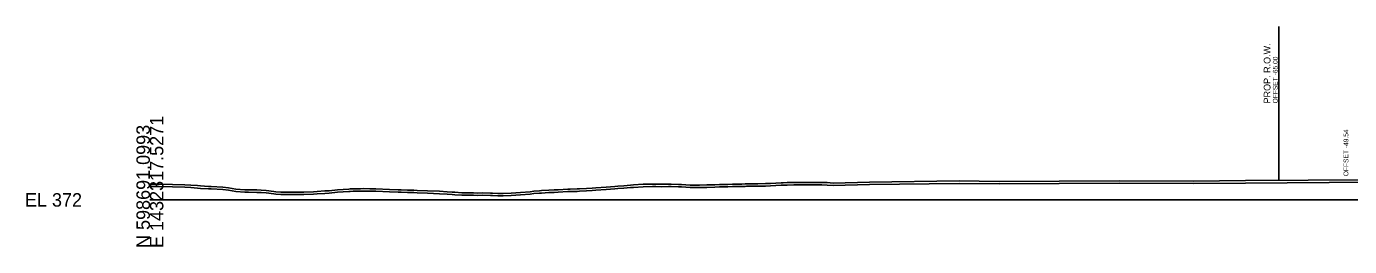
# Model space of a CAD drawing. Extents: x -26 to 2203, y -10 to 12201.
# Drawn here: x -25.7 to 249.7, y 8490.3 to 8536.1 of the extents above; entities that cross this region are included whole.
import ezdxf

# ---------------------------------------------------------------- set-up
doc = ezdxf.new("R2010")
doc.units = 0
for name, color, linetype in [('DESIGN - ROW - Right-of-Way and Easement Labels', 7, 'Continuous'), ('DESIGN - ROW - Right-of-Way Linework', 7, 'Continuous'), ('DESIGN - SHEET - Light Grid', 7, 'Continuous'), ('DESIGN - TYPICAL - Slope Tie Text', 7, 'Continuous'), ('SURVEY - GROUND - Bottom of Topsoil Layer', 7, 'Continuous'), ('SURVEY - GROUND - Top of Ground', 7, 'Continuous')]:
    doc.layers.add(name, color=color, linetype=linetype)

msp = doc.modelspace()

# ---------------------------------------------------------------- linework, layer by layer
at = {"layer": 'DESIGN - ROW - Right-of-Way Linework'}
msp.add_line((235, 8504.06), (235, 8536.06), dxfattribs=at)
at = {"layer": 'DESIGN - SHEET - Light Grid'}
msp.add_line((0, 8500), (300, 8500), dxfattribs=at)
at = {"layer": 'SURVEY - GROUND - Bottom of Topsoil Layer'}
for p, q in [((0, 8502.79), (0.47, 8502.78)), ((0.47, 8502.78), (1.96, 8502.76)), ((1.96, 8502.76), (4.69, 8502.7)), ((4.69, 8502.7), (7.26, 8502.66)), ((7.26, 8502.66), (8.55, 8502.56)), ((8.55, 8502.56), (9.91, 8502.47)), ((9.91, 8502.47), (10.51, 8502.4)), ((10.51, 8502.4), (12.21, 8502.31)), ((12.21, 8502.31), (12.75, 8502.27)), ((12.75, 8502.27), (15.21, 8502.15)), ((15.21, 8502.15), (16.39, 8502.01)), ((16.39, 8502.01), (17.86, 8501.72)), ((17.86, 8501.72), (19.74, 8501.62)), ((19.74, 8501.62), (20.51, 8501.59)), ((20.51, 8501.59), (22.27, 8501.57)), ((22.27, 8501.57), (23.16, 8501.51)), ((37.3, 8501.41), (39.07, 8501.58)), ((39.07, 8501.58), (41.39, 8501.75)), ((41.39, 8501.75), (41.72, 8501.78)), ((41.72, 8501.78), (42.32, 8501.79)), ((42.32, 8501.79), (43.83, 8501.83)), ((43.83, 8501.83), (44.37, 8501.84)), ((44.37, 8501.84), (45.79, 8501.83)), ((45.79, 8501.83), (47.02, 8501.79)), ((47.02, 8501.79), (49.84, 8501.67)), ((49.84, 8501.67), (51.68, 8501.6)), ((51.68, 8501.6), (52.32, 8501.6)), ((52.32, 8501.6), (53.64, 8501.54)), ((83.04, 8501.51), (84.13, 8501.56)), ((84.13, 8501.56), (85, 8501.61)), ((85, 8501.61), (86.96, 8501.72)), ((86.96, 8501.72), (87.48, 8501.73)), ((87.48, 8501.73), (88.92, 8501.78)), ((88.92, 8501.78), (89.43, 8501.81)), ((89.43, 8501.81), (90.88, 8501.9)), ((90.88, 8501.9), (92.08, 8501.96)), ((92.08, 8501.96), (92.84, 8502.04)), ((92.84, 8502.04), (95, 8502.17)), ((95, 8502.17), (96.76, 8502.31)), ((96.76, 8502.31), (97.38, 8502.34)), ((97.38, 8502.34), (98.67, 8502.44)), ((98.67, 8502.44), (100.03, 8502.55)), ((100.03, 8502.55), (100.68, 8502.61)), ((100.68, 8502.61), (102.68, 8502.75)), ((102.68, 8502.75), (104.6, 8502.76)), ((104.6, 8502.76), (105.33, 8502.78)), ((105.33, 8502.78), (106.56, 8502.75)), ((106.56, 8502.75), (107.98, 8502.78)), ((107.98, 8502.78), (108.52, 8502.77)), ((108.52, 8502.77), (110.06, 8502.72)), ((110.06, 8502.72), (110.63, 8502.7)), ((110.63, 8502.7), (112.44, 8502.59)), ((112.44, 8502.59), (113.28, 8502.56)), ((113.28, 8502.56), (114.4, 8502.55)), ((114.4, 8502.55), (115.94, 8502.6)), ((115.94, 8502.6), (117.58, 8502.66)), ((117.58, 8502.66), (118.59, 8502.69)), ((118.59, 8502.69), (120.29, 8502.73)), ((120.29, 8502.73), (121.24, 8502.76)), ((121.24, 8502.76), (123.22, 8502.8)), ((123.22, 8502.8), (123.89, 8502.82)), ((123.89, 8502.82), (124.21, 8502.83)), ((124.21, 8502.83), (125.11, 8502.84)), ((125.11, 8502.84), (126.17, 8502.85)), ((126.17, 8502.85), (126.54, 8502.87)), ((126.54, 8502.87), (128.13, 8502.88)), ((128.13, 8502.88), (129.19, 8502.94)), ((129.19, 8502.94), (131.41, 8503.04)), ((131.41, 8503.04), (131.84, 8503.05)), ((131.84, 8503.05), (132.64, 8503.09)), ((132.64, 8503.09), (134.01, 8503.12)), ((134.01, 8503.12), (134.49, 8503.14)), ((134.49, 8503.14), (135.5, 8503.15)), ((135.5, 8503.15), (137.14, 8503.15)), ((137.14, 8503.15), (137.93, 8503.14)), ((137.93, 8503.14), (139.89, 8503.13)), ((139.89, 8503.13), (140.97, 8503.09)), ((140.97, 8503.09), (142.25, 8503.01)), ((142.25, 8503.01), (149.78, 8503.21)), ((149.78, 8503.21), (168.45, 8503.43)), ((168.45, 8503.43), (176.81, 8503.36)), ((176.81, 8503.36), (201.76, 8503.46)), ((201.76, 8503.46), (217.25, 8503.38)), ((217.25, 8503.38), (228.08, 8503.51)), ((228.08, 8503.51), (254.14, 8503.7)), ((23.16, 8501.51), (24.23, 8501.47)), ((24.23, 8501.47), (25.81, 8501.24)), ((25.81, 8501.24), (26.19, 8501.21)), ((26.19, 8501.21), (27.26, 8501.13)), ((27.26, 8501.13), (28.15, 8501.09)), ((28.15, 8501.09), (28.46, 8501.09)), ((28.46, 8501.09), (30.11, 8501.11)), ((30.11, 8501.11), (31.11, 8501.13)), ((31.11, 8501.13), (32.07, 8501.11)), ((32.07, 8501.11), (34.03, 8501.19)), ((34.03, 8501.19), (34.79, 8501.27)), ((34.79, 8501.27), (36.42, 8501.36)), ((36.42, 8501.36), (37.3, 8501.41)), ((53.64, 8501.54), (54.97, 8501.51)), ((54.97, 8501.51), (55.6, 8501.48)), ((55.6, 8501.48), (57.76, 8501.39)), ((57.76, 8501.39), (60.27, 8501.29)), ((60.27, 8501.29), (61.85, 8501.19)), ((61.85, 8501.19), (62.92, 8501.13)), ((62.92, 8501.13), (63.44, 8501.08)), ((63.44, 8501.08), (64.9, 8501)), ((64.9, 8501), (65.57, 8500.98)), ((65.57, 8500.98), (67.36, 8500.97)), ((67.36, 8500.97), (68.22, 8500.93)), ((68.22, 8500.93), (69.32, 8500.95)), ((69.32, 8500.95), (70.87, 8500.88)), ((70.87, 8500.88), (71.28, 8500.89)), ((71.28, 8500.89), (72.42, 8500.86)), ((72.42, 8500.86), (73.53, 8500.83)), ((73.53, 8500.83), (75.2, 8500.92)), ((75.2, 8500.92), (76.18, 8500.95)), ((76.18, 8500.95), (77.16, 8501.03)), ((77.16, 8501.03), (79.12, 8501.21)), ((79.12, 8501.21), (79.95, 8501.3)), ((79.95, 8501.3), (81.08, 8501.4)), ((81.08, 8501.4), (81.48, 8501.43)), ((81.48, 8501.43), (83.04, 8501.51))]:
    msp.add_line(p, q, dxfattribs=at)
at = {"layer": 'SURVEY - GROUND - Top of Ground'}
for p, q in [((0, 8503.29), (0.47, 8503.28)), ((0.47, 8503.28), (1.96, 8503.26)), ((1.96, 8503.26), (4.69, 8503.2)), ((4.69, 8503.2), (7.26, 8503.16)), ((7.26, 8503.16), (8.55, 8503.06)), ((8.55, 8503.06), (9.91, 8502.97)), ((9.91, 8502.97), (10.51, 8502.9)), ((10.51, 8502.9), (12.21, 8502.81)), ((12.21, 8502.81), (12.75, 8502.77)), ((12.75, 8502.77), (15.21, 8502.65)), ((15.21, 8502.65), (16.39, 8502.51)), ((16.39, 8502.51), (17.86, 8502.22)), ((17.86, 8502.22), (19.74, 8502.12)), ((19.74, 8502.12), (20.51, 8502.09)), ((20.51, 8502.09), (22.27, 8502.07)), ((22.27, 8502.07), (23.16, 8502.01)), ((23.16, 8502.01), (24.23, 8501.97)), ((24.23, 8501.97), (25.81, 8501.74)), ((25.81, 8501.74), (26.19, 8501.71)), ((26.19, 8501.71), (27.26, 8501.63)), ((27.26, 8501.63), (28.15, 8501.59)), ((28.15, 8501.59), (28.46, 8501.59)), ((28.46, 8501.59), (30.11, 8501.61)), ((30.11, 8501.61), (31.11, 8501.63)), ((31.11, 8501.63), (32.07, 8501.61)), ((32.07, 8501.61), (34.03, 8501.69)), ((34.03, 8501.69), (34.79, 8501.77)), ((34.79, 8501.77), (36.42, 8501.86)), ((36.42, 8501.86), (37.3, 8501.91)), ((37.3, 8501.91), (39.07, 8502.08)), ((39.07, 8502.08), (41.39, 8502.25)), ((41.39, 8502.25), (41.72, 8502.28)), ((41.72, 8502.28), (42.32, 8502.29)), ((42.32, 8502.29), (43.83, 8502.33)), ((43.83, 8502.33), (44.37, 8502.34)), ((44.37, 8502.34), (45.79, 8502.33)), ((45.79, 8502.33), (47.02, 8502.29)), ((47.02, 8502.29), (49.84, 8502.17)), ((49.84, 8502.17), (51.68, 8502.1)), ((51.68, 8502.1), (52.32, 8502.1)), ((52.32, 8502.1), (53.64, 8502.04)), ((53.64, 8502.04), (54.97, 8502.01)), ((54.97, 8502.01), (55.6, 8501.98)), ((55.6, 8501.98), (57.76, 8501.89)), ((57.76, 8501.89), (60.27, 8501.79)), ((60.27, 8501.79), (61.85, 8501.69)), ((61.85, 8501.69), (62.92, 8501.63)), ((62.92, 8501.63), (63.44, 8501.58)), ((63.44, 8501.58), (64.9, 8501.5)), ((77.16, 8501.53), (79.12, 8501.71)), ((79.12, 8501.71), (79.95, 8501.8)), ((79.95, 8501.8), (81.08, 8501.9)), ((81.08, 8501.9), (81.48, 8501.93)), ((81.48, 8501.93), (83.04, 8502.01)), ((83.04, 8502.01), (84.13, 8502.06)), ((84.13, 8502.06), (85, 8502.11)), ((85, 8502.11), (86.96, 8502.22)), ((86.96, 8502.22), (87.48, 8502.23)), ((87.48, 8502.23), (88.92, 8502.28)), ((88.92, 8502.28), (89.43, 8502.31)), ((89.43, 8502.31), (90.88, 8502.4)), ((90.88, 8502.4), (92.08, 8502.46)), ((92.08, 8502.46), (92.84, 8502.54)), ((92.84, 8502.54), (95, 8502.67)), ((95, 8502.67), (96.76, 8502.81)), ((96.76, 8502.81), (97.38, 8502.84)), ((97.38, 8502.84), (98.67, 8502.94)), ((98.67, 8502.94), (100.03, 8503.05)), ((100.03, 8503.05), (100.68, 8503.11)), ((100.68, 8503.11), (102.68, 8503.25)), ((102.68, 8503.25), (104.6, 8503.26)), ((104.6, 8503.26), (105.33, 8503.28)), ((105.33, 8503.28), (106.56, 8503.25)), ((106.56, 8503.25), (107.98, 8503.28)), ((107.98, 8503.28), (108.52, 8503.27)), ((108.52, 8503.27), (110.06, 8503.22)), ((110.06, 8503.22), (110.63, 8503.2)), ((110.63, 8503.2), (112.44, 8503.09)), ((112.44, 8503.09), (113.28, 8503.06)), ((113.28, 8503.06), (114.4, 8503.05)), ((114.4, 8503.05), (115.94, 8503.1)), ((115.94, 8503.1), (117.58, 8503.16)), ((117.58, 8503.16), (118.59, 8503.19)), ((118.59, 8503.19), (120.29, 8503.23)), ((120.29, 8503.23), (121.24, 8503.26)), ((121.24, 8503.26), (123.22, 8503.3)), ((123.22, 8503.3), (123.89, 8503.32)), ((123.89, 8503.32), (124.21, 8503.33)), ((124.21, 8503.33), (125.11, 8503.34)), ((125.11, 8503.34), (126.17, 8503.35)), ((126.17, 8503.35), (126.54, 8503.37)), ((126.54, 8503.37), (128.13, 8503.38)), ((128.13, 8503.38), (129.19, 8503.44)), ((129.19, 8503.44), (131.41, 8503.54)), ((131.41, 8503.54), (131.84, 8503.55)), ((131.84, 8503.55), (132.64, 8503.59)), ((132.64, 8503.59), (134.01, 8503.62)), ((134.01, 8503.62), (134.49, 8503.64)), ((134.49, 8503.64), (135.5, 8503.65)), ((135.5, 8503.65), (137.14, 8503.65)), ((137.14, 8503.65), (137.93, 8503.64)), ((137.93, 8503.64), (139.89, 8503.63)), ((139.89, 8503.63), (140.97, 8503.59)), ((140.97, 8503.59), (142.25, 8503.51)), ((142.25, 8503.51), (149.78, 8503.71)), ((149.78, 8503.71), (168.45, 8503.93)), ((168.45, 8503.93), (176.81, 8503.86)), ((176.81, 8503.86), (201.76, 8503.96)), ((201.76, 8503.96), (217.25, 8503.88)), ((217.25, 8503.88), (228.08, 8504.01)), ((228.08, 8504.01), (254.14, 8504.2)), ((64.9, 8501.5), (65.57, 8501.48)), ((65.57, 8501.48), (67.36, 8501.47)), ((67.36, 8501.47), (68.22, 8501.43)), ((68.22, 8501.43), (69.32, 8501.45)), ((69.32, 8501.45), (70.87, 8501.38)), ((70.87, 8501.38), (71.28, 8501.39)), ((71.28, 8501.39), (72.42, 8501.36)), ((72.42, 8501.36), (73.53, 8501.33)), ((73.53, 8501.33), (75.2, 8501.42)), ((75.2, 8501.42), (76.18, 8501.45)), ((76.18, 8501.45), (77.16, 8501.53))]:
    msp.add_line(p, q, dxfattribs=at)

# ---------------------------------------------------------------- texts
at = {"layer": 'DESIGN - ROW - Right-of-Way and Easement Labels'}
for s, height, p in [('PROP. R.O.W.', 1.4, (233.25, 8520.06)), ('OFFSET -65.00', 1, (234.75, 8520.06))]:
    msp.add_text(s, height=height, rotation=90, dxfattribs=at).set_placement(p)
at = {"layer": 'DESIGN - SHEET - Light Grid'}
for s, p in [('N 598691.0993', (0, 8490)), ('E 1432317.5271', (2.8, 8490))]:
    msp.add_text(s, height=2.8, rotation=90, dxfattribs=at).set_placement(p)
msp.add_text('EL 372', height=2.8, dxfattribs=at).set_placement((-26, 8498.6))
at = {"layer": 'DESIGN - TYPICAL - Slope Tie Text'}
msp.add_text('OFFSET -49.54', height=1, rotation=90, dxfattribs=at).set_placement((249.46, 8504.92))

doc.saveas('drawing.dxf')
